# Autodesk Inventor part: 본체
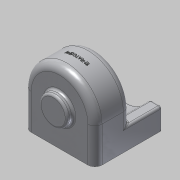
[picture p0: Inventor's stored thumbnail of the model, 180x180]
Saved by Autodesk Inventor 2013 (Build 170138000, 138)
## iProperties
Created: 2015-02
Part Number: 본체
Material: 알루미늄 6061
Document SubType Name: Modeling
Designer: Administrator
Density: 1 g/cm^3
Author: Administrator
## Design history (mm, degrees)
sketch "스케치1"
  geometry: L1 (-50, -50)-(50, -50); L2 (-50, -50)-(-50, 0); L3 (50, -50)-(50, 0); A1 r 50 centre (0, 0) between (-50, 0) and (50, 0); 2 further points
  constraints: 6 end point, 2 point on circle, 2 tangent, 1 centre point, 1 coincident, 1 horizontal, 1 midpoint, 1 vertical alignment
  dimensions: "d0" = 100 diameter of A1; "d1" = 100 distance of L1.start L1.end; "d2" = 50 distance from line of L1 point (0, 0)
extrude "돌출1" new body sketch "스케치1" distance "d3" = 95; taper "d4" = 0 deg
sketch "스케치2"
  geometry: L1 (50, 50)-(-50, 50) reference; L2 (-50, 50)-(-50, 0) reference; L3 (50, 0)-(50, 50) reference; L4 (50, 50)-(-50, 50); L5 (-50, 50)-(-50, 20); L6 (-50, 20)-(50, 20); L7 (50, 20)-(50, 50); L8 (50, 20)-(50, 0); L9 (-50, 20)-(-50, 0); C1 r 40 at (0, 0); C2 r 50 at (0, 0); A1 r 50 centre (0, 0) between (-50, 0) and (50, 0) reference
  constraints: 12 end point, 2 centre point, 2 coincident, 2 parallel, 2 tangent, 1 collinear, 1 horizontal, 1 perpendicular, 1 point on line
  dimensions: "d5" = 80 diameter of C1; "d6" = 30 distance of L5.end L4.end; "d7" = 100 diameter of C2
extrude "돌출2" cut sketch "스케치2" distance "d8" = 45; taper "d9" = 0 deg
sketch "스케치3"
  geometry: C1 r 20 at (0, 0); A1 r 50 centre (0, 0) between (50, 0) and (-50, 0) reference
  constraints: 1 centre point, 1 coincident
  dimensions: "d10" = 40 diameter of C1
extrude "돌출3" join sketch "스케치3" distance "d11" = 9; taper "d12" = 0 deg
sketch "스케치4"
  geometry: C1 r 25 at (0, 0); A1 r 50 centre (0, 0) between (-50, 0) and (50, 0) reference
  constraints: 1 centre point, 1 coincident
  dimensions: "d13" = 50 diameter of C1
extrude "돌출4" join sketch "스케치4" distance "d14" = 10; taper "d15" = 0 deg
feature "면 기울기1" dims angle "d16" = 20 deg
node "작업 평면1"
sketch "스케치5" dims "d17" = 92
  geometry: L1 (50, 50)-(50, 0) reference; L2 (-50, 0)-(-50, 50) reference; L3 (-50, 50)-(50, 50) reference; L4 (46, 50)-(-46, 50); L5 (-46, 50)-(-46, 0); L6 (-46, 0)-(46, 0); L7 (46, 0)-(46, 50); A1 r 50 centre (0, 0) between (-50, 0) and (50, 0) reference; 3 further points
  constraints: 8 end point, 2 coincident, 2 parallel, 1 horizontal, 1 horizontal alignment, 1 midpoint, 1 perpendicular, 1 point on line, 2 other
extrude "돌출5" cut sketch "스케치5" stored distance "d18" = 42; taper "d19" = 0 deg
hole "구멍1" diameter "d22" = 28; stored, may be unused: countersink angle "d26" = 90 deg, drill point angle "d28" = 0 deg; dims "d20" = 10, "d21" = 10, "d23" = 6, "d24" = 4, "d25" = 2, "d27" = 10
hole "구멍2" diameter "d31" = 20; stored, may be unused: countersink angle "d35" = 90 deg, drill point angle "d37" = 0 deg; dims "d29" = 10, "d30" = 10, "d32" = 6, "d33" = 4, "d34" = 2, "d36" = 4
hole "구멍3" diameter "d40" = 28; stored, may be unused: countersink angle "d44" = 90 deg, drill point angle "d46" = 0 deg; dims "d38" = 10, "d39" = 10, "d41" = 6, "d42" = 4, "d43" = 2, "d45" = 8
hole "구멍4" diameter "d49" = 20; stored, may be unused: countersink angle "d53" = 90 deg, drill point angle "d55" = 0 deg; dims "d47" = 10, "d48" = 10, "d50" = 6, "d51" = 4, "d52" = 2, "d54" = 2
sketch "스케치6"
  geometry: C1 r 14 at (0, 0) reference; 1 further point
  constraints: 1 vertical alignment
  dimensions: "d56" = 18 distance of C1.centre point (0, -18)
hole "구멍5" sketch "스케치6" at (0, -18) diameter "d57" = 2.459; stored, may be unused: countersink angle "d61" = 90 deg, drill point angle "d63" = 118 deg; dims "d58" = 6, "d59" = 4, "d60" = 2, "d62" = 9
fillet "모깎기1" dims "d67" = 10
fillet "모깎기2" dims "d68" = 6
chamfer "모따기1" distance "d69" = 1; stored, may be unused: second distance "d70" = 2, angle "d71" = 45 deg
chamfer "모따기2" distance "d72" = 1; stored, may be unused: second distance "d73" = 2, angle "d74" = 45 deg
fillet "모깎기3" dims "d75" = 0.3
fillet "모깎기4" dims "d76" = 0.3
fillet "모깎기5" dims "d77" = 3
fillet "모깎기6" dims "d78" = 3
fillet "모깎기7" dims "d79" = 3
sketch "스케치7"
  geometry: L1 (90, 10)-(90, 92) reference; L2 (-7, 95)-(87, 95) reference; 5 further points
  constraints: 2 horizontal alignment, 2 vertical alignment
  dimensions: "d80" = 33 distance of point (81.75, 53) point (81.75, 86); "d82" = 83.5 distance of point (-1.75, 86) point (81.75, 86); "d83" = 8.25 distance from line of L1 point (81.75, 86); "d84" = 9 distance from line of L2 point (-1.75, 86)
hole "구멍6" sketch "스케치7" at (-1.75, 86), (-1.75, 53), (81.75, 86), (81.75, 53) diameter "d85" = 5.134; stored, may be unused: countersink angle "d89" = 90 deg, drill point angle "d91" = 118 deg; dims "d86" = 10, "d87" = 4, "d88" = 2, "d90" = 13
node "작업 평면2"
sketch "스케치8"
  geometry: 2 further points
  constraints: 1 vertical alignment, 1 other
  dimensions: "d92" = 25 distance of point (0, 25) point (0, 0)
feature "엠보싱1" sketch "스케치8" dims "d1" = 100, "d8" = 45, "d93" = 0.5, "d94" = 0
node "솔리드1"
pattern_circular "원형 패턴1" dims angle "d65" = 360 deg
node "절단 모서리 투영1"
